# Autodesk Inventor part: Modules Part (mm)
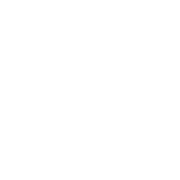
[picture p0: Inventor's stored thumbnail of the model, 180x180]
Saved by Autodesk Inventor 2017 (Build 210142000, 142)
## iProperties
Created: 2014-08
Part Number: Modules Part (mm)
Material: Generic
Document SubType Name: Modeling
Designer: Wally
Density: 1 g/cm^3
Appearance: Default
Author: Wally
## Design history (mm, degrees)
node "Sketch1"
